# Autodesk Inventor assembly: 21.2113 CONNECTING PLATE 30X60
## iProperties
Created: 2012-10
Part Number: 21.2113 CONNECTING PLATE 30X60
Document SubType Name: Assembly
Designer: Administrator
Author: Administrator
